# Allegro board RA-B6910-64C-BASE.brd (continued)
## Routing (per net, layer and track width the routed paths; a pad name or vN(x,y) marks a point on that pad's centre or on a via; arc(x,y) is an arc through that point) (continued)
VDD5V: length 15.8
  TOP w0.508: C113.1 387.09,55.17 ; R265.1 385.92,46.05 385.56,46.41 385.56,51.74 387.21,53.39 ; C114.2 387.09,54.03 ; R204.1 405.86,53.8 405.6,54.05 C103.1 v1(406.9,54.66)
  BOTTOM w0.381: v3(399.29,22.73) v1(400.18,22.73) ; v1(388.61,55.3) 388.62,55.31 v3(388.62,56.26) ; v1(406.9,54.66) 406.91,54.67 v3(406.91,55.75)
  vias: v1(390.01,55.3) v1(390.01,54.41) v1(390.01,53.52) v1(391.28,55.3) v1(398.64,24.31) v1(399.15,25.2) v1(399.53,24.31) v1(400.17,23.68)
VDD5V_EN: length 7.8
  TOP w0.381: Q7.3 407.79,57.08 406.67,55.96 R198.1 R193.2 403.88,55.96 403.09,55.17 U4.5
VDD12V: length 660.1
  TOP w0.381: R196.1 v1(412.61,56.21) ; C131.2 9.92,44.99 ; C131.2 11.39,44.99 ; C131.2 10.66,45.77 ; R262.1 v1(388.74,43.61) ; C79.2 v1(3.35,122.15) ; C151.2 47.77,45.11 ; C151.2 48.63,46.03 ; C151.2 49.37,45.11 ; R261.1 v1(395.59,42.98) ; C81.2 v1(4.88,122.15) ; R199.1 v1(413.76,52.5) ; R193.1 v1(404.61,57.84)
  TOP w0.508: J9.A18 24.52,127.07 ; J9.A18 25.68,125.91 ; J9.A18 24.52,124.76 ; J8.A16 387.06,125.91 ; J8.A16 385.9,124.76 ; J8.A16 384.74,125.91 ; J8.A16 385.9,127.07 ; J8.A13 393.52,127.07 ; J8.A13 393.52,124.76 ; J8.A13 394.68,125.91 ; J8.A13 392.36,125.91 ; J1.9 53.27,68.05 ; J1.9 50.24,68.05 ; J1.9 51.76,69.56 ; J1.9 51.76,66.54 ; 385.9,127.3 J8.B16 ; J8.B16 387.06,128.45 ; J8.B16 384.74,128.45 ; J5.8 113.04,170.95 ; J5.8 111.98,172.01 ; J5.8 110.92,170.95 ; 44.84,127.3 J9.B10 43.68,128.45 ; J3.9 15.76,69.56 ; J3.9 15.76,66.54 ; J3.9 17.27,68.05 ; J3.9 14.24,68.05 ; 42.3,124.76 J9.A11 ; J9.A11 41.14,125.91 ; J9.A11 43.46,125.91 ; J9.A11 42.3,127.07 ; 62.84,68.05 J1.6 ; J1.6 64.35,69.56 ; J1.6 65.87,68.05 ; J1.6 64.35,66.54 ; 19.96,66.54 J3.8 ; J3.8 21.47,68.05 ; J3.8 19.96,69.56 ; J3.8 18.44,68.05 ; J8.A12 396.06,127.07 ; J8.A12 397.22,125.91 ; J8.A12 396.06,124.76 ; J8.A12 394.9,125.91 ; 46.04,68.05 J1.10 ; J1.10 49.07,68.05 ; J1.10 47.55,69.56 ; J1.10 47.55,66.54 ; 26.84,68.05 J3.6 ; J3.6 29.87,68.05 ; J3.6 28.36,66.54 ; J3.6 28.36,69.56 ; J8.A15 389.6,125.91 ; J8.A15 388.44,124.76 ; J8.A15 388.44,127.07 ; J8.A15 387.28,125.91 ; 390.98,124.76 J8.A14 ; J8.A14 390.98,127.07 ; J8.A14 392.14,125.91 ; J8.A14 389.82,125.91 ; 58.64,68.05 J1.7 ; J1.7 61.67,68.05 ; J1.7 60.16,69.56 ; J1.7 60.16,66.54 ; 39.76,127.3 J9.B12 ; J9.B12 40.92,128.45 ; J9.B12 38.6,128.45 ; 37.22,127.3 J9.B13 ; J9.B13 36.06,128.45 ; J9.B13 38.38,128.45 ; C94.1 402.58,45.77 ; v1(363.52,121.77) 363.78,121.51 C68.2 ; 25.68,128.45 J9.B18 24.52,127.3 ; 208.76,170.95 J4.7 209.82,172.01 ; J9.A10 44.84,127.07 ; J9.A10 44.84,124.76 ; J9.A10 43.68,125.91 ; 11.55,66.54 J3.10 ; J3.10 11.55,69.56 ; J3.10 10.04,68.05 ; J3.10 13.07,68.05 ; 389.82,128.45 J8.B14 ; J8.B14 390.98,127.3 ; J8.B14 392.14,128.45 ; J9.A16 30.76,125.91 ; J9.A16 29.6,124.76 ; J9.A16 29.6,127.07 ; J9.A16 28.44,125.91 ; 113.46,170.95 J5.7 114.52,172.01 ; 383.36,124.76 J8.A17 ; J8.A17 382.2,125.91 ; J8.A17 384.52,125.91 ; J8.A17 383.36,127.07 ; 388.44,127.3 J8.B15 ; J8.B15 387.28,128.45 ; J8.B15 389.6,128.45 ; J8.B13 394.68,128.45 ; J8.B13 393.52,127.3 ; J8.B13 392.36,128.45 ; U9.A40 v1(165.71,50.13) ; 399.98,128.45 J8.B10 401.14,127.3 ; 32.14,127.3 J9.B15 ; J9.B15 30.98,128.45 ; J9.B15 33.3,128.45 ; 38.6,125.91 J9.A12 ; J9.A12 40.92,125.91 ; J9.A12 39.76,124.76 ; J9.A12 39.76,127.07 ; J8.A18 381.98,125.91 ; J8.A18 380.82,127.07 ; J8.A18 380.82,124.76 ; 398.6,127.3 J8.B11 ; J8.B11 397.44,128.45 ; J8.B11 399.76,128.45 ; 206.22,170.95 J4.8 ; J4.8 208.34,170.95 ; J4.8 207.28,172.01 ; 28.44,128.45 J9.B16 ; J9.B16 29.6,127.3 ; J9.B16 30.76,128.45 ; J9.A13 38.38,125.91 ; J9.A13 37.22,124.76 ; J9.A13 37.22,127.07 ; J9.A13 36.06,125.91 ; 34.68,124.76 J9.A14 ; J9.A14 35.84,125.91 ; J9.A14 34.68,127.07 ; J9.A14 33.52,125.91 ; 304.06,170.95 J2.7 305.12,172.01 ; 381.98,128.45 J8.B18 380.82,127.3 ; U9.B40 v1(164.44,50.13) ; 32.14,124.76 J9.A15 ; J9.A15 32.14,127.07 ; J9.A15 30.98,125.91 ; J9.A15 33.3,125.91 ; C67.2 v1(362.25,121.77) ; 396.06,127.3 J8.B12 ; J8.B12 397.22,128.45 ; J8.B12 394.9,128.45 ; J9.A17 27.06,127.07 ; J9.A17 28.22,125.91 ; J9.A17 27.06,124.76 ; J9.A17 25.9,125.91 ; J8.A11 398.6,127.07 ; J8.A11 399.76,125.91 ; J8.A11 397.44,125.91 ; J8.A11 398.6,124.76 ; J9.B11 43.46,128.45 ; J9.B11 41.14,128.45 ; J9.B11 42.3,127.3 ; 382.2,128.45 J8.B17 ; J8.B17 384.52,128.45 ; J8.B17 383.36,127.3 ; 27.06,127.3 J9.B17 ; J9.B17 28.22,128.45 ; J9.B17 25.9,128.45 ; 54.44,68.05 J1.8 ; J1.8 55.95,66.54 ; J1.8 57.47,68.05 ; J1.8 55.95,69.56 ; J2.8 302.58,172.01 ; J2.8 301.52,170.95 ; J2.8 303.64,170.95 ; U9.D40 161.9,50.16 v1(161.91,50.15) ; v1(163.18,50.15) 163.17,50.16 U9.C40 ; J8.A10 401.14,127.07 ; J8.A10 399.98,125.91 ; J8.A10 401.14,124.76 ; 22.64,68.05 J3.7 ; J3.7 24.16,69.56 ; J3.7 24.16,66.54 ; J3.7 25.67,68.05 ; 33.52,128.45 J9.B14 ; J9.B14 34.68,127.3 ; J9.B14 35.84,128.45 ; C108.1 v1(398.64,52.76)
  TOP w0.559: U3.3 402.13,43.8 402.45,44.12 ; v1(397.63,53.9) 397.95,54.22 U4.3
  GND1 w0.508: 382.2,128.45 J8.B17 ; J8.B17 384.52,128.45 ; J8.B17 383.36,129.61 ; J8.B17 383.36,127.3 ; J8.A13 393.52,127.07 ; J8.A13 392.36,125.91 ; J8.A13 394.68,125.91 ; J8.A13 393.52,124.76 ; J8.A18 381.98,125.91 ; J8.A18 380.82,127.07 ; J8.A18 380.82,124.76 ; 398.6,127.3 J8.B11 ; J8.B11 397.44,128.45 ; J8.B11 399.76,128.45 ; J8.B11 398.6,129.61 ; J8.A14 392.14,125.91 ; J8.A14 390.98,124.76 ; J8.A14 390.98,127.07 ; J8.A14 389.82,125.91 ; J8.A11 399.76,125.91 ; J8.A11 398.6,127.07 ; J8.A11 397.44,125.91 ; J8.A11 398.6,124.76 ; 384.74,128.45 J8.B16 ; J8.B16 385.9,127.3 ; J8.B16 385.9,129.61 ; J8.B16 387.06,128.45 ; J8.B12 396.06,129.61 ; J8.B12 397.22,128.45 ; J8.B12 394.9,128.45 ; J8.B12 396.06,127.3 ; J8.A15 388.44,127.07 ; J8.A15 389.6,125.91 ; J8.A15 387.28,125.91 ; J8.A15 388.44,124.76 ; J8.B15 389.6,128.45 ; J8.B15 388.44,127.3 ; J8.B15 388.44,129.61 ; J8.B15 387.28,128.45 ; J8.A16 387.06,125.91 ; J8.A16 384.74,125.91 ; J8.A16 385.9,127.07 ; J8.A16 385.9,124.76 ; J8.B13 393.52,129.61 ; J8.B13 393.52,127.3 ; J8.B13 394.68,128.45 ; J8.B13 392.36,128.45 ; J8.B14 392.14,128.45 ; J8.B14 390.98,129.61 ; J8.B14 390.98,127.3 ; J8.B14 389.82,128.45 ; 396.06,124.76 J8.A12 ; J8.A12 394.9,125.91 ; J8.A12 397.22,125.91 ; J8.A12 396.06,127.07 ; J8.A17 383.36,127.07 ; J8.A17 384.52,125.91 ; J8.A17 383.36,124.76 ; J8.A17 382.2,125.91 ; 399.98,125.91 J8.A10 ; J8.A10 401.14,127.07 ; J8.A10 401.14,124.76 ; 399.98,128.45 J8.B10 ; J8.B10 401.14,127.3 ; J8.B10 401.14,129.61 ; 380.82,127.3 J8.B18 381.98,128.45
  SIG1 w0.508: 60.16,66.54 J1.7 ; J1.7 60.16,69.56 ; J1.7 58.64,68.05 ; J1.7 61.67,68.05 ; J8.A14 392.14,125.91 ; J8.A14 390.98,124.76 ; J8.A14 390.98,127.07 ; J8.A14 389.82,125.91 ; 51.76,66.54 J1.9 ; J1.9 51.76,69.56 ; J1.9 53.27,68.05 ; J1.9 50.24,68.05 ; J9.B13 38.38,128.45 ; J9.B13 36.06,128.45 ; J9.B13 37.22,127.3 ; J9.B14 35.84,128.45 ; J9.B14 33.52,128.45 ; J9.B14 34.68,127.3 ; 24.52,127.3 J9.B18 25.68,128.45 ; J1.8 55.95,69.56 ; J1.8 55.95,66.54 ; J1.8 57.47,68.05 ; J1.8 54.44,68.05 ; 64.35,66.54 J1.6 ; J1.6 62.84,68.05 ; J1.6 65.87,68.05 ; J1.6 64.35,69.56 ; 34.68,124.76 J9.A14 ; J9.A14 33.52,125.91 ; J9.A14 34.68,127.07 ; J9.A14 35.84,125.91 ; 385.9,124.76 J8.A16 ; J8.A16 385.9,127.07 ; J8.A16 387.06,125.91 ; J8.A16 384.74,125.91 ; J9.A17 28.22,125.91 ; J9.A17 25.9,125.91 ; J9.A17 27.06,127.07 ; J9.A17 27.06,124.76 ; 14.24,68.05 J3.9 ; J3.9 15.76,66.54 ; J3.9 17.27,68.05 ; J3.9 15.76,69.56 ; J9.A16 29.6,127.07 ; J9.A16 28.44,125.91 ; J9.A16 30.76,125.91 ; J9.A16 29.6,124.76 ; J9.A12 40.92,125.91 ; J9.A12 39.76,127.07 ; J9.A12 39.76,124.76 ; J9.A12 38.6,125.91 ; J9.A15 32.14,127.07 ; J9.A15 32.14,124.76 ; J9.A15 30.98,125.91 ; J9.A15 33.3,125.91 ; J8.A18 381.98,125.91 ; J8.A18 380.82,124.76 ; J8.A18 380.82,127.07 ; J9.A18 25.68,125.91 ; J9.A18 24.52,127.07 ; J9.A18 24.52,124.76 ; 46.04,68.05 J1.10 ; J1.10 47.55,69.56 ; J1.10 47.55,66.54 ; J1.10 49.07,68.05 ; 396.06,124.76 J8.A12 ; J8.A12 394.9,125.91 ; J8.A12 397.22,125.91 ; J8.A12 396.06,127.07 ; 41.14,125.91 J9.A11 ; J9.A11 42.3,127.07 ; J9.A11 42.3,124.76 ; J9.A11 43.46,125.91 ; J8.A11 398.6,127.07 ; J8.A11 397.44,125.91 ; J8.A11 398.6,124.76 ; J8.A11 399.76,125.91 ; 392.36,125.91 J8.A13 ; J8.A13 393.52,124.76 ; J8.A13 394.68,125.91 ; J8.A13 393.52,127.07 ; 10.04,68.05 J3.10 ; J3.10 13.07,68.05 ; J3.10 11.55,66.54 ; J3.10 11.55,69.56 ; J3.7 25.67,68.05 ; J3.7 24.16,66.54 ; J3.7 24.16,69.56 ; J3.7 22.64,68.05 ; J8.A10 401.14,127.07 ; J8.A10 401.14,124.76 ; J8.A10 399.98,125.91 ; 36.06,125.91 J9.A13 ; J9.A13 37.22,124.76 ; J9.A13 37.22,127.07 ; J9.A13 38.38,125.91 ; 399.98,128.45 J8.B10 401.14,127.3 ; J9.B12 40.92,128.45 ; J9.B12 38.6,128.45 ; J9.B12 39.76,127.3 ; 28.44,128.45 J9.B16 ; J9.B16 30.76,128.45 ; J9.B16 29.6,127.3 ; 396.06,127.3 J8.B12 ; J8.B12 394.9,128.45 ; J8.B12 397.22,128.45 ; J9.B15 33.3,128.45 ; J9.B15 32.14,127.3 ; J9.B15 30.98,128.45 ; J8.B16 387.06,128.45 ; J8.B16 384.74,128.45 ; J8.B16 385.9,127.3 ; 387.28,128.45 J8.B15 ; J8.B15 389.6,128.45 ; J8.B15 388.44,127.3 ; 382.2,125.91 J8.A17 ; J8.A17 383.36,127.07 ; J8.A17 383.36,124.76 ; J8.A17 384.52,125.91 ; J3.8 19.96,69.56 ; J3.8 19.96,66.54 ; J3.8 18.44,68.05 ; J3.8 21.47,68.05 ; 44.84,124.76 J9.A10 ; J9.A10 44.84,127.07 ; J9.A10 43.68,125.91 ; 44.84,127.3 J9.B10 43.68,128.45 ; 28.36,66.54 J3.6 ; J3.6 28.36,69.56 ; J3.6 26.84,68.05 ; J3.6 29.87,68.05 ; J9.B11 43.46,128.45 ; J9.B11 41.14,128.45 ; J9.B11 42.3,127.3 ; J9.B17 28.22,128.45 ; J9.B17 25.9,128.45 ; J9.B17 27.06,127.3 ; J8.B13 394.68,128.45 ; J8.B13 393.52,127.3 ; J8.B13 392.36,128.45 ; 387.28,125.91 J8.A15 ; J8.A15 388.44,124.76 ; J8.A15 388.44,127.07 ; J8.A15 389.6,125.91 ; 397.44,128.45 J8.B11 ; J8.B11 398.6,127.3 ; J8.B11 399.76,128.45 ; 389.82,128.45 J8.B14 ; J8.B14 390.98,127.3 ; J8.B14 392.14,128.45 ; 383.36,127.3 J8.B17 ; J8.B17 384.52,128.45 ; J8.B17 382.2,128.45 ; 380.82,127.3 J8.B18 381.98,128.45
  SIG1 w1.016: J8.A24 365.58,123.75
  SIG2 w0.508: 58.64,68.05 J1.7 ; J1.7 61.67,68.05 ; J1.7 60.16,66.54 ; J1.7 60.16,69.56 ; 41.14,125.91 J9.A11 ; J9.A11 43.46,125.91 ; J9.A11 42.3,124.76 ; J9.A11 42.3,127.07 ; J3.7 24.16,69.56 ; J3.7 25.67,68.05 ; J3.7 24.16,66.54 ; J3.7 22.64,68.05 ; 11.55,66.54 J3.10 ; J3.10 10.04,68.05 ; J3.10 13.07,68.05 ; J3.10 11.55,69.56 ; J9.A15 33.3,125.91 ; J9.A15 32.14,124.76 ; J9.A15 30.98,125.91 ; J9.A15 32.14,127.07 ; J9.B16 30.76,128.45 ; J9.B16 28.44,128.45 ; J9.B16 29.6,127.3 ; 50.24,68.05 J1.9 ; J1.9 51.76,69.56 ; J1.9 51.76,66.54 ; J1.9 53.27,68.05 ; J9.B17 28.22,128.45 ; J9.B17 27.06,127.3 ; J9.B17 25.9,128.45 ; 15.76,66.54 J3.9 ; J3.9 15.76,69.56 ; J3.9 14.24,68.05 ; J3.9 17.27,68.05 ; 64.35,66.54 J1.6 ; J1.6 64.35,69.56 ; J1.6 62.84,68.05 ; J9.A12 39.76,127.07 ; J9.A12 39.76,124.76 ; J9.A12 40.92,125.91 ; J9.A12 38.6,125.91 ; 33.52,125.91 J9.A14 ; J9.A14 34.68,127.07 ; J9.A14 35.84,125.91 ; J9.A14 34.68,124.76 ; J9.A16 29.6,127.07 ; J9.A16 30.76,125.91 ; J9.A16 28.44,125.91 ; J9.A16 29.6,124.76 ; 39.76,127.3 J9.B12 ; J9.B12 38.6,128.45 ; J9.B12 40.92,128.45 ; 42.3,127.3 J9.B11 ; J9.B11 43.46,128.45 ; J9.B11 41.14,128.45 ; 25.68,128.45 J9.B18 24.52,127.3 ; J9.A13 37.22,127.07 ; J9.A13 36.06,125.91 ; J9.A13 38.38,125.91 ; J9.A13 37.22,124.76 ; 43.68,125.91 J9.A10 ; J9.A10 44.84,127.07 ; J9.A10 44.84,124.76 ; J9.A18 25.68,125.91 ; J9.A18 24.52,127.07 ; J9.A18 24.52,124.76 ; 55.95,66.54 J1.8 ; J1.8 55.95,69.56 ; J1.8 57.47,68.05 ; J1.8 54.44,68.05 ; 32.14,127.3 J9.B15 ; J9.B15 33.3,128.45 ; J9.B15 30.98,128.45 ; 26.84,68.05 J3.6 ; J3.6 28.36,69.56 ; J3.6 28.36,66.54 ; J3.6 29.87,68.05 ; 33.52,128.45 J9.B14 ; J9.B14 35.84,128.45 ; J9.B14 34.68,127.3 ; 27.06,124.76 J9.A17 ; J9.A17 28.22,125.91 ; J9.A17 27.06,127.07 ; J9.A17 25.9,125.91 ; 19.96,66.54 J3.8 ; J3.8 18.44,68.05 ; J3.8 19.96,69.56 ; J3.8 21.47,68.05 ; 36.06,128.45 J9.B13 ; J9.B13 37.22,127.3 ; J9.B13 38.38,128.45 ; J1.10 49.07,68.05 ; J1.10 47.55,66.54 ; J1.10 46.04,68.05 ; J1.10 47.55,69.56 ; 44.84,127.3 J9.B10 43.68,128.45
  SIG2 w1.016: 9.28,124.15 J9.A24
  BOTTOM w0.381: v3(392.68,106.43) 392.68,107.74 v4(392.67,107.75) ; v3(53.72,114.05) 53.72,115.74 v4(53.71,115.75) ; v1(403.21,46.79) 403.21,48 v3(403.23,48.01) ; v3(314.58,99.19) 314.58,98.11 v1(314.57,98.1) ; v3(46.47,114.05) v4(46.47,115.75) ; v4(28.82,115.75) 28.83,115.74 v3(28.83,114.17) ; v3(317.25,99.19) 317.25,98.11 v1(317.24,98.1) ; v3(389.13,106.43) 389.13,107.87 v4(389.12,107.88) ; v3(399.8,52.7) 398.7,52.7 v1(398.64,52.76) ; v4(385.94,109.15) 385.89,109.09 v3(384.18,109.09) ; v3(36.45,114.3) 36.45,115.74 v4(36.44,115.75) ; v1(319.9,98.1) 319.91,98.11 v3(319.91,99.19) ; v3(60.83,114.3) 60.83,115.74 v4(60.82,115.75) ; v1(395.21,52.76) 395.27,52.7 v3(396.37,52.7) ; v4(397.75,107.75) 397.76,107.74 v3(397.76,106.43)
  vias: v1(314.57,97.21) v1(314.57,96.32) v1(314.57,95.43) v1(315.46,98.1) v1(315.46,97.21) v1(315.46,96.32) v1(315.46,95.43) v1(316.35,98.1) v1(316.35,97.21) v1(316.35,96.32) v1(316.35,95.43) v1(317.24,97.21) v1(317.24,96.32) v1(317.24,95.43) v1(318.12,98.1) v1(318.12,97.21) v1(318.12,96.32) v1(318.12,95.43) v1(319.01,98.1) v1(319.01,97.21) v1(319.01,96.32) v1(319.01,95.43) v1(319.9,97.21) v1(319.9,96.32) v1(319.9,95.43) v1(320.79,98.1) v1(320.79,97.21) v1(320.79,96.32) v1(320.79,95.43) v1(321.68,98.1) v1(321.68,97.21) v1(321.68,96.32) v1(321.68,95.43) v1(395.21,53.65) v1(397.5,52.76) v1(403.21,45.65) v1(403.21,44.5) v1(404.23,46.79) v4(28.63,123.67) v4(28.75,120.11) v4(28.82,117.78) v4(29.77,121.89) v4(31.17,123.67) v4(31.29,120.11) v4(31.36,117.78) v4(31.36,115.75) v4(32.31,121.89) v4(33.71,123.67) v4(33.83,120.11) v4(33.9,117.78) v4(33.9,115.75) v4(34.85,121.89) v4(36.25,123.67) v4(36.37,120.11) v4(36.44,117.78) v4(37.39,121.89) v4(38.79,123.67) v4(38.91,120.11) v4(38.98,117.78) v4(38.98,115.75) v4(39.93,121.89) v4(41.33,123.67) v4(41.45,120.11) v4(41.52,117.78) v4(41.52,115.75) v4(42.47,121.89) v4(43.74,123.67) v4(43.87,120.11) v4(43.93,117.78) v4(43.93,115.75) v4(45.01,121.89) v4(46.41,123.42) v4(46.53,119.86) v4(46.47,117.78) v4(47.55,121.38) v4(48.82,122.91) v4(48.82,119.86) v4(48.76,117.78) v4(48.76,115.75) v4(50.09,121.38) v4(51.23,119.86) v4(51.17,117.78) v4(51.17,115.75) v4(51.36,122.91) v4(52.63,121.38) v4(53.71,117.78) v4(53.77,119.86) v4(53.9,122.91) v4(55.17,121.38) v4(55.93,119.81) v4(55.87,117.78) v4(55.87,115.75) v4(56.13,122.94) v4(57.33,121.51) v4(58.34,119.86) v4(58.28,117.78) v4(58.28,115.75) v4(58.6,123.04) v4(59.87,121.51) v4(60.82,117.78) v4(60.88,119.86) v4(61.14,123.04) v4(62.41,121.51) v4(63.11,117.78) v4(63.11,115.75) v4(63.17,119.86) v4(63.68,123.04) v4(64.95,121.64) v4(65.65,117.78) v4(65.71,119.86) v4(66.22,123.04) v4(67.49,121.64) v4(67.93,119.69) v4(68.76,123.04) v4(69.9,121.64) v4(385.75,123.42) v4(385.75,121.64) v4(385.82,119.81) v4(385.94,117.53) v4(385.94,116.13) v4(385.94,114.61) v4(385.94,113.21) v4(385.94,111.94) v4(385.94,110.54) v4(385.94,107.88) v4(387.59,117.53) v4(387.59,116.13) v4(387.59,114.61) v4(387.59,113.21) v4(387.59,111.94) v4(387.59,110.54) v4(387.59,109.15) v4(387.59,107.88) v4(388.29,123.42) v4(388.29,121.64) v4(388.36,119.81) v4(389.12,117.53) v4(389.12,116.13) v4(389.12,114.61) v4(389.12,113.21) v4(389.12,111.94) v4(389.12,110.54) v4(389.12,109.15) v4(390.83,123.42) v4(390.83,121.64) v4(390.9,117.4) v4(390.9,116) v4(390.9,114.48) v4(390.9,113.08) v4(390.9,111.81) v4(390.9,110.42) v4(390.9,109.02) v4(390.9,107.75) v4(392.67,117.4) v4(392.67,116) v4(392.67,114.48) v4(392.67,113.08) v4(392.67,111.81) v4(392.67,110.42) v4(392.67,109.02) v4(393.37,123.42) v4(393.37,121.64) v4(393.44,119.81) v4(394.32,117.4) v4(394.32,116) v4(394.32,114.48) v4(394.32,113.08) v4(394.32,111.81) v4(394.32,110.42) v4(394.32,109.02) v4(394.32,107.75) v4(395.91,123.42) v4(395.91,121.64) v4(395.98,119.81) v4(395.98,117.4) v4(395.98,116) v4(395.98,114.48) v4(395.98,113.08) v4(395.98,111.81) v4(395.98,110.42) v4(395.98,109.02) v4(395.98,107.75) v4(397.69,121.64) v4(397.75,119.81) v4(397.75,117.4) v4(397.75,116) v4(397.75,114.48) v4(397.75,113.08) v4(397.75,111.81) v4(397.75,110.42) v4(397.75,109.02)
VDD12VSB: length 403.6
  TOP w0.305: 371.91,124 371.91,127.16 J8.B21 ; J9.B21 15.62,127.18 15.62,124.38
  TOP w0.508: 371.91,124 369.62,121.72 C77.2 368.73,120.95 368.63,120.85 v2(368.48,120.85) C74.2 ; 15.62,124.38 13.72,122.48 13.1,122.48 12.12,121.5 C87.2 13.09,120.98 13.19,121.08 C89.2 15.06,121.08 15.8,120.34 v1(15.8,116.71) 15.8,115.84 22.11,109.53 78.23,109.53 v1(79.84,111.14)
  SIG2 w0.508: v1(79.84,111.14) 84.42,115.72 85.91,115.72 89.78,119.59 92.28,119.59 95.94,123.25 99.57,123.25 100.19,123.87 103.92,123.87 104.23,124.19 109.21,124.19 109.59,124.57 114.73,124.57 120.13,119.17 120.13,118.55 126.03,112.65 144.72,112.65 146.29,114.23 157.34,114.23 160.64,110.92 340.98,110.92 348.4,118.34 359.97,118.34 361.59,119.96 365.37,119.96 366.26,120.85 v2(368.48,120.85)
  BOTTOM w0.381: v1(15.8,116.71) 15.8,116.28 v3(16.38,115.7)
9548_RST#: length 37
  TOP w0.201: R128.2 v2(128.39,152.83) ; R240.2 v1(97.91,153.09) 98.02,152.97 U8.3
  SIG1 w0.15: v1(108.83,152.58) 105.15,152.58 104.38,153.34 98.16,153.34 v1(97.91,153.09)
  SIG2 w0.16: v2(128.39,152.83) 127.88,153.34 121.97,153.34 120.92,154.39 119.97,154.39 119.06,155.3 115.65,155.3 115.25,154.9 111.15,154.9 v1(108.83,152.58)
ALL_RESET#: length 197.3
  TOP w0.201: U1.107 117.47,149.78 116.96,150.29 R109.1 116.55,151.21 116.37,151.39 116.37,153.06 116.96,153.65 R110.1 113.3,153.88 v2(112.89,153.47) ; U9.C26 162.55,69.4 161.58,69.4 159.37,67.19 v1(159.37,64.84)
  SIG2 w0.16: v2(112.89,153.47) 111.64,153.47 105.64,147.47 105.64,136.87 103.24,134.47 103.24,130.58 101.84,129.17 95.02,129.17 91.15,125.31 90.47,125.31 89.18,124.02 84.22,124.02 72.61,112.41 72.61,100 83.6,89.01 96.83,89.01 98.45,87.4 122.26,87.4 139.43,70.22 148.26,70.22 153.64,64.84 v1(159.37,64.84)
BMC_9641_INT#: length 121.9
  TOP w0.201: U9.A2 166.25,99.82 v1(174.93,99.82) ; v2(105.17,134.5) 104.87,134.8 R303.1
  SIG1 w0.15: v1(174.93,99.82) 174.93,126.38 173.94,127.37 150.47,127.37 141.9,118.8 124.96,118.8 123.18,120.59 118.15,120.59 113.78,124.95 113.78,133.28 113.02,134.04 112,134.04 111.54,134.5 v2(105.17,134.5)
BMC_I2C_RST#: length 208.2
  TOP w0.201: U9.D36 159.73,56.09 v1(158.99,56.82) ; v2(122.43,155.07) 122.43,155.57 122.76,155.91 R117.2
  SIG2 w0.16: v1(158.99,56.82) 157.56,56.82 148.38,65.99 139.13,65.99 120.8,84.32 83.42,84.32 69.54,98.2 69.54,113.69 83.57,127.71 87.85,127.71 88.81,128.67 90.17,128.67 92.09,130.59 92.09,131.77 92.57,132.25 94.34,132.25 94.6,132.51 99.75,132.51 100.17,132.93 100.17,136.37 103.6,139.8 103.6,150.45 109.78,156.64 112.01,156.64 112.83,157.46 120.82,157.46 122.43,155.85 v2(122.43,155.07)
BMC_I2C_SCL: length 194.7
  TOP w0.127: v1(163.8,63.07) 163.8,60.53 U9.B33
  TOP w0.201: R309.2 90.03,126.8 89.5,127.34 v1(89.45,127.34) ; U10.5 101.91,133.35 102.59,134.02 105.57,134.02 105.68,134.13 105.68,136.55 104.89,137.34 104.3,137.34 v2(103.98,137.67) 104.92,138.61 107.05,138.61 107.71,137.95 109.31,137.95 109.44,138.08 R115.1 109.86,138.48 110.57,137.77 112.57,137.77 112.89,138.1 U1.126
  SIG2 w0.16: v2(103.98,137.67) 101.5,135.19 101.5,132.36 100.05,130.91 94.3,130.91 90.72,127.34 v1(89.45,127.34) 89.45,126.74 89.09,126.38 84.12,126.38 70.88,113.13 70.88,98.76 83.98,85.66 121.36,85.66 139.69,67.33 148.94,67.33 153.31,62.96 161.25,62.96 161.81,63.52 163.4,63.52 163.8,63.12 v1(163.8,63.07)
BMC_I2C_SDA: length 182.9
  TOP w0.127: U9.D33 v1(161.26,59.26)
  TOP w0.201: R301.1 104.49,136.22 104.13,136.58 103.72,136.58 v2(102.68,137.62) 102.65,137.64 102.65,137.92 104.83,140.09 109.25,140.09 109.44,139.91 R123.1 109.84,139.5 110.86,138.48 R16.2 ; R310.2 91.05,126.99 v1(90.03,128)
  SIG2 w0.16: v2(102.68,137.62) 100.84,135.78 100.84,132.65 100.03,131.84 95.33,131.84 95.07,131.59 94.03,131.59 90.45,128 v1(90.03,128) 89.09,128 88.13,127.05 83.84,127.05 70.21,113.41 70.21,98.48 83.7,84.99 121.08,84.99 139.41,66.66 148.66,66.66 153.03,62.29 158.23,62.29 v1(161.26,59.26)
BMC_RESERVE1: length 120.4
  TOP w0.127: U9.C38 v1(162.53,52.91)
  TOP w0.201: v2(147.01,122.35) 147.01,127.62 145.67,128.96 R249.2
  SIG1 w0.15: v2(147.01,122.35) 151.18,126.52 173.32,126.52 173.98,125.85 173.98,60.75 168.83,55.6 168.83,54.13 167.17,52.47 164.02,52.47 163.57,52.91 v1(162.53,52.91)
CPLD3.3V: length 529.5
  TOP w0.229: C17.1 135.09,124.36 134.79,124.67 134.79,126.24 134.47,126.56 U1.36 ; C8.2 126.94,151.21 126.69,150.95 126.69,149.84 126.97,149.55 U1.88 ; v1(138.29,128.83) 138.03,129.1 U1.37 ; U1.102 119.97,150.79 C9.2 ; U1.7 119.97,125.91 119.75,125.69 v1(119.75,125.2) ; v1(113.02,139.6) U1.123 ; U1.30 131.47,125.82 131.05,125.4 v1(131.05,125.02) ; U1.108 116.97,149.24 116.42,149.79 115.94,149.79 v1(115.31,150.42) ; U1.144 112.65,129.1 112.51,128.96 C6.2 ; C48.2 124.32,124.61 124.32,125.91 124.47,126.06 U1.16 ; U1.79 131.47,149.62 131.03,150.07 131.03,151.03 131.21,151.21 C2.2 ; v1(137.91,135.69) 137.5,136.1 U1.51 ; U1.135 113.77,133.6 113.2,133.02 v1(112.79,133.02) ; C4.2 138.57,143.69 137.53,143.69 137.44,143.6 U1.66 ; v1(113.53,141.91) 113.71,142.1 U1.118 ; U1.72 138.15,146.6 138.67,147.12 C3.2
  TOP w0.254: C117.2 99.32,143.01 U8.24 ; U2.20 57.01,84.38 56.63,84 C63.2
  TOP w0.305: U10.16 94.36,130.75 93.33,129.72 C154.2
  TOP w0.381: v1(235.07,175.85) R346.1 234.28,175.82 R347.2 ; R299.2 v1(90.92,134.47) ; 142.74,87.43 141.13,89.04 141.13,91.66 143.75,94.29 R256.2 R275.2 R274.2 ; 142.74,87.43 144.41,89.11 R257.2 ; 142.74,87.43 142.74,82.35 142.74,82.35 142.74,80.8 144.42,79.13 R258.1 143.63,78.35 142.74,77.46 142.74,65.16 143.33,64.57 R260.1 144.41,58.57 144.42,58.57 v1(144.42,53.87) ; R296.2 v1(90.92,135.82) ; R160.2 134.23,122.86 v1(134.48,122.61) ; R318.2 v1(107.94,135.69) ; R283.1 110.23,157.94 v1(109.72,158.45) ; v1(107.81,145.16) 108.13,145.47 R133.1 ; R230.1 94.99,155.25 v1(95.37,155.63) ; R352.2 139.05,164.8 R351.1 v1(139.08,163.88) ; C6.2 C22.2 ; C22.2 v1(112.89,127.94) ; C22.2 C19.2 ; R113.2 v1(119.24,152.83) ; R17.2 110.66,140.52 v1(110.35,140.82) ; R166.2 119.75,120.07 ; v1(153.44,173.07) 153.29,172.93 U7.8 ; v1(142.33,146.74) R273.2 ; R232.1 v1(92.7,155.63) ; C9.2 120.39,150.68 v1(120.64,150.42) ; R242.1 v1(99.94,155.63) R284.2 ; R158.2 122.67,120.13 ; v1(138.29,143.06) 138.7,143.06 C4.2 ; R255.1 v1(53.71,89.72) ; R143.2 v1(134.97,152.17) ; R89.2 v1(107.69,141.91) ; R294.2 91.05,137.09 v1(90.92,136.96) ; v1(129.66,120.58) R277.1 R333.2 ; R243.1 96.89,138.99 v1(95.87,137.98) ; C154.2 C155.2 92.55,127.92 92.32,127.69 91.3,127.69 89.04,129.95 v1(89.04,130.02) 89.02,130.04 R304.1 ; C116.1 154.2,173.71 v1(153.95,173.96) ; R161.2 v1(133.21,122.61) ; R329.2 329.15,173.03 R328.1 v1(329.94,173.05) ; R271.2 v1(140.58,145.09) ; R131.1 v1(107.81,144.2) ; R47.2 v1(34.15,85.4) ; v1(138.29,127.82) C49.2 C157.2 ; C51.2 v1(119.75,125.2) ; R164.2 v1(126.99,122.61) ; R345.2 117.08,120.45 117.85,119.69 ; R356.2 v1(132.68,54.05) ; R150.1 v1(53.71,85.65) ; R154.2 121.02,120.16 ; C3.2 C7.2 v1(138.17,148.14) ; R268.2 142.33,132.5 v1(142.52,132.69) 142.33,132.88 R270.2 ; R292.2 91.05,138.48 v1(90.92,138.36) ; 124.58,120.2 R339.2 125.19,120.86 ; D2.3 v1(110.1,147.53) ; R122.2 v1(123.81,152.83) ; C2.2 131.56,150.78 v1(131.82,150.52) ; C63.2 v1(55.46,83.11) ; R240.1 v1(97.91,155.63) ; R46.2 v1(34.15,94.16) ; C20.2 C5.2 v1(136.39,125.15) ; R254.1 v1(53.71,86.67) ; C66.1 C1.2 114.8,150.93 v1(115.31,150.42) ; C117.2 v1(99.94,143.18) ; C10.2 v1(34.15,90.1) ; C65.1 v1(113.53,141.91) ; v1(127.98,122.68) 128.13,122.83 R163.2 ; R252.1 v1(68.06,89.08) ; R229.1 v1(95.37,158.3) ; C48.2 124.58,124.51 v1(125.08,125.02) ; R115.2 R123.2 v1(107.69,139.5) ; v1(137.91,135.69) 138.67,134.93 C23.2 ; R112.2 v1(144.01,124.89) ; R305.2 90.41,130.74 v1(90.29,130.86) ; C64.1 112.92,139.5 v1(113.02,139.6) ; v1(156.36,169.52) R224.2 R225.2 ; v1(138.29,128.83) C16.1 ; C92.1 394.99,44.86 394.73,45.11 R195.1 ; C17.1 135.24,125 v1(135.4,125.15) ; C8.2 v1(127.24,150.42) ; R110.2 116.12,154.84 v1(115.94,154.66) ; v1(112.79,133.02) C21.2 ; R167.2 v1(121.02,122.61) ; v1(105.27,132.51) R297.1 ; R231.1 v1(92.7,158.3) ; C18.1 v1(138.17,149.15) ; C156.1 v1(115.81,152.96) ; v1(131.05,125.02) C50.2 ; R220.2 v1(156.36,171.55) ; R319.2 v1(107.94,136.96) ; R306.1 88.25,133.53 v1(87.87,133.91) ; R241.1 v1(100.95,155.63) ; R228.1 v1(96.64,155.63) ; v1(110.35,130.99) R118.2 ; R281.2 v1(236.21,169.22) ; R227.1 v1(97.41,157.51)
  TOP w0.508: C92.1 393.94,44.25 393.67,44.52 393.67,48.3 394.07,48.69 401.56,48.69 402.45,49.58 v1(412.61,49.58) ; 414.14,39.55 415.15,38.53 X22.1 ; v1(413.5,44.12) 413.37,44.25 C100.2 ; 414.26,44 414.52,44.25 C99.1 ; C97.1 410.45,44.78 v1(411.24,44) ; v1(229.89,167.95) R280.1 228.72,167.19 228.18,166.65 214.21,166.65 v1(212.59,165.03) ; v1(304.79,166.3) 306.34,164.75 v1(322.6,164.75) 326.86,164.75 327.52,165.41 R278.2 ; R194.1 414.49,40.85 ; C98.1 411.98,44.25
  TOP w1.016: v4(67.68,81.46) v4(55.46,81.46) 52.95,81.46 50.41,84 v4(34.15,84) 26.15,84 23.74,86.41 23.74,90.1 24.75,91.11 J7.4
  SIG1 w0.381: v1(329.94,173.05) 329.94,172.09 v1(322.6,164.75) ; v1(68.06,89.08) 67.21,88.23 67.21,84.6 67.68,84.13 v4(67.68,81.46)
  SIG1 w0.508: v4(55.46,81.46) v1(55.46,83.11) 55.46,83.52 53.71,85.27 v1(53.71,85.65) v1(53.71,86.67) v1(53.71,89.72) ; v1(235.07,175.85) 235.07,175.16 229.89,169.98 v1(229.89,167.95) ; v4(34.15,84) v1(34.15,85.4) 34.79,86.03 34.79,89.46 v1(34.15,90.1) v1(34.15,94.16)
  SIG2 w0.381: v1(139.08,163.88) 136.13,160.94 136.13,153.22
  SIG2 w0.508: 161.28,168.2 181.22,168.2 184.39,165.03 v1(212.59,165.03) ; v1(229.89,167.95) 234.94,167.95 v1(236.21,169.22) 239.38,169.22 241.61,166.99 304.1,166.99 v1(304.79,166.3)
  vias: v1(126.14,120.61) v1(127.16,120.61) v1(128.13,120.61) v1(159.5,168.71) v1(159.5,167.57) v1(160.14,154.87) v1(160.14,153.98) v1(160.52,168.71) v1(160.52,167.57) v1(161.15,154.87) v1(161.15,153.98) v1(188.46,53.14) v1(188.46,52.25) v1(188.46,51.36) v1(188.46,50.47) v1(189.35,53.14) v1(189.35,52.25) v1(189.35,51.36) v1(189.35,50.47) v1(189.85,102.29) v1(189.85,101.4) v1(189.85,100.51) v1(189.85,99.62) v1(190.24,53.14) v1(190.24,52.25) v1(190.24,51.36) v1(190.24,50.47) v1(190.36,123.62) v1(190.36,122.74) v1(190.36,121.85) v1(190.36,120.96) v1(190.74,102.29) v1(190.74,101.4) v1(190.74,100.51) v1(190.74,99.62) v1(191.12,53.14) v1(191.12,52.25) v1(191.12,51.36) v1(191.12,50.47) v1(191.25,123.62) v1(191.25,122.74) v1(191.25,121.85) v1(191.25,120.96) v1(191.63,102.29) v1(191.63,101.4) v1(191.63,100.51) v1(191.63,99.62) v1(192.01,53.14) v1(192.01,52.25) v1(192.01,51.36) v1(192.01,50.47) v1(192.14,123.62) v1(192.14,122.74) v1(192.14,121.85) v1(192.14,120.96) v1(192.52,102.29) v1(192.52,101.4) v1(192.52,100.51) v1(192.52,99.62) v1(192.9,53.14) v1(192.9,52.25) v1(192.9,51.36) v1(192.9,50.47) v1(193.03,123.62) v1(193.03,122.74) v1(193.03,121.85) v1(193.03,120.96) v1(193.41,102.29) v1(193.41,101.4) v1(193.41,100.51) v1(193.41,99.62) v1(193.92,123.62) v1(193.92,122.74) v1(193.92,121.85) v1(193.92,120.96) v1(194.3,102.29) v1(194.3,101.4) v1(194.3,100.51) v1(194.3,99.62) v1(194.81,123.62) v1(194.81,122.74) v1(194.81,121.85) v1(194.81,120.96) v1(412.61,44.12) v1(413.5,42.98)
CPLD3.3V_EN: length 8.5
  TOP w0.381: Q9.3 v1(393.16,41.71) 393.51,41.35 R264.1 R261.2 396.13,41.35 396.51,41.73 396.51,42.12 397.25,42.85 U3.5
  BOTTOM w0.381: v3(392.3,41.78) 393.08,41.78 v1(393.16,41.71)
CPLD_DOWNLOAD_OK: length 10.1
  TOP w0.201: U1.106 117.97,150.17 117.49,150.65 117.49,155.27 118.1,155.88 R119.1 117.43,156.16 v1(117.09,155.83)
  BOTTOM w0.201: v1(117.09,155.83) 116.97,155.7 v3(116.21,155.7)
CPLD_TCK: length 120.6
  TOP w0.201: R48.1 R45.1 36.06,87.66 46.07,87.66 53.33,94.92 59.43,94.92 63.74,99.24 v2(64.54,99.24) ; R146.2 67.93,91.24 68.26,91.57 70.1,91.57 70.6,92.07 70.6,93.91 v1(69.1,95.4) ; U1.131 v1(113.4,135.6)
  SIG1 w0.15: v2(64.54,99.24) 64.1,98.81 64.1,97.02 66.35,94.77 68.47,94.77 v1(69.1,95.4) 69.37,95.4 75.23,101.27 76.24,101.27 79.01,104.04 79.01,108.1 87.05,116.13 87.2,116.13 96.7,125.63 96.7,133.34 99.43,136.07 107.68,136.07 107.75,136.15 112.85,136.15 v1(113.4,135.6)
CPLD_TDI: length 119.7
  TOP w0.201: U1.136 113.96,133.1 113.07,132.21 109.74,132.21 v1(109.59,132.36) ; R51.1 R47.1 50.66,85.4 53.58,82.48 67.73,82.48 69.18,83.93 69.18,84.54 v2(68.7,85.02) 67.93,85.78 R151.2
  SIG1 w0.15: v1(109.59,132.36) 109.11,131.88 107.18,131.88 105.51,133.55 101.19,133.55 100.95,133.78 98.61,133.78 97.73,132.91 97.73,125.2 90.24,117.71 90.24,114.63 89.77,114.16 87.87,114.16 80.99,107.28 80.99,102.26 78.86,100.13 78.86,99.2 69.75,90.1 69.55,90.1 68.95,89.5 68.95,88.83 68.32,88.19 68.32,85.4 v2(68.7,85.02)
CPLD_TDO: length 131.5
  TOP w0.201: v2(68.95,94.11) 68.57,94.49 65.32,94.49 64.21,93.38 62.49,93.38 60.65,91.54 60.65,88.52 59.75,87.63 U2.15 ; v1(108.6,132.34) R4.2 ; J7.3 48.52,91.11 53.04,95.63 58.61,95.63 63.11,100.13 v1(64.51,100.13)
  SIG1 w0.15: v1(108.6,132.34) 107.01,133.93 103.22,133.93 102.61,134.55 98.83,134.55 97.35,133.07 97.35,125.36 87.47,115.47 87.32,115.47 79.67,107.82 79.67,103.77 70.01,94.11 v2(68.95,94.11) 66.08,94.11 63.44,96.75 63.44,99.08 64.49,100.13 v1(64.51,100.13)
CPLD_TMS: length 116.1
  TOP w0.201: v1(64.51,101.02) 63.28,101.02 58.4,96.14 52.83,96.14 50.85,94.16 R46.1 R49.1 ; v1(113.65,136.45) 114.01,136.1 U1.130 ; R148.2 67.74,95.18 v2(68.27,95.71)
  SIG1 w0.15: v1(113.65,136.45) 112.69,137.42 107.65,137.42 106.97,136.73 99.16,136.73 95.23,132.8 95.23,129.32 93.64,127.72 93.64,123.5 89.54,119.4 83.69,119.4 80.65,116.35 80.65,110.66 78.36,108.37 78.36,104.83 78.03,104.5 77.53,104.5 69.22,96.19 68.75,96.19 v2(68.27,95.71) 68.17,95.61 66.74,95.61 65.19,97.16 65.19,100.33 v1(64.51,101.02)
CPU_9641_INT#: length 122.3
  TOP w0.201: U9.A3 166.51,98.8 v2(174.93,98.8) ; R290.1 v1(104.49,129.72)
  SIG1 w0.15: v1(104.49,129.72) 104.49,129.87 105.82,131.21 109.62,131.21 110.35,131.94 111.94,131.94 112.32,131.56 112.32,124.9 117.01,120.21 123.02,120.21 124.81,118.42 142.06,118.42 150.63,126.99 173.65,126.99 174.45,126.19 174.45,99.28 v2(174.93,98.8)
CPU_I2C_RST#: length 86.5
  TOP w0.201: YJ1.A1_1 v1(89.08,87.45) ; v2(145.38,80.06) C149.1 ; U9.C17 162.53,80.85 158.53,80.85 v1(157.47,81.91)
  SIG1 w0.15: v1(89.08,87.45) 89.44,87.1 137.14,87.1 142.99,81.25 144.19,81.25 v2(145.38,80.06) 155.63,80.06 v1(157.47,81.91)
CPU_I2C_SCL: length 169.8
  TOP w0.201: v1(121.83,119.05) 121.83,121.41 121.43,121.82 R154.1 121.82,122.62 121.82,125.19 121.97,125.34 U1.11 ; v2(104.61,125.2) R307.2 104.61,127.21 104.34,127.47 103.13,127.47 99.68,130.92 99.68,131.5 100.23,132.05 U10.3 ; U9.D13 161.54,85.65 159.06,85.65 v1(155.32,81.91)
  SIG1 w0.15: v1(155.32,81.91) 143.26,81.91 137.41,87.76 93.76,87.76 92.32,89.2 85.12,89.2 82.51,91.8 82.51,106.8 88.22,112.5 90.98,112.5 103.67,125.2 v2(104.61,125.2) 105.19,125.78 110.45,125.78 117.18,119.05 v1(121.83,119.05)
CPU_I2C_SDA: length 165.1
  TOP w0.201: v1(156.46,81.91) 159.14,84.6 162.6,84.6 U9.C14 ; v1(123.43,119.15) 123.43,121.47 123.08,121.82 R158.1 122.67,122.74 122.54,122.86 R157.2 ; R291.1 104.82,131.5 105.02,131.3 105.02,129.47 104.61,129.06 R308.2 105.27,128.2 105.53,127.94 105.53,127.31 106.7,126.14 v2(106.7,125.18)
  SIG1 w0.15: v1(156.46,81.91) 155.26,83.11 142.99,83.11 137.69,88.41 94.03,88.41 92.59,89.86 85.39,89.86 83.17,92.08 83.17,106.53 88.49,111.85 91.25,111.85 102.33,122.92 104.44,122.92 v2(106.7,125.18) 107.24,124.64 109.91,124.64 117.08,117.46 122.09,117.46 123.43,118.81 v1(123.43,119.15)
CPU_KR_RDN0: length 63.9
  TOP w0.127: U9.C9 v1(162.53,91.01)
  SIG1 w0.102: 108.06,98.69 108.04,98.69 107.99,98.64 106.95,98.64 arc(106.94,98.63) 106.94,98.63 arc(106.82,98.6) 106.7,98.56 arc(106.65,98.53) 106.6,98.5 arc(106.58,98.49) 106.57,98.48 arc(106.56,98.48) 106.55,98.47 arc(106.54,98.47) 106.53,98.47 arc(106.52,98.47) 106.51,98.47 YJ1.B7_2
  SIG1 w0.119: v1(162.53,91.01) 162.57,91.06 163.06,91.06 163.39,91.39 163.39,93.22 162.83,93.78 159.82,93.78 158.32,95.28 119.27,95.28 115.86,98.69 108.06,98.69
CPU_KR_RDN1: length 78.8
  TOP w0.127: U9.C12 v1(162.53,87.2)
  SIG1 w0.102: YJ1.B7_1 94.52,98.47 arc(94.53,98.47) 94.54,98.47 arc(94.54,98.47) 94.55,98.47 arc(94.55,98.47) 94.56,98.48 arc(94.57,98.48) 94.59,98.49 arc(94.81,98.6) 95.05,98.64 95.93,98.64 95.98,98.69 96,98.69
  SIG1 w0.119: v1(162.53,87.2) 162.7,87.37 163.06,87.37 163.4,87.71 163.4,88.92 162.98,89.34 159.22,89.34 157.04,91.52 112.44,91.52 112.11,91.19 102.15,91.19 99.28,94.06 99.28,96.5 97.09,98.69 96,98.69
CPU_KR_RDP0: length 63.9
  TOP w0.127: U9.C8 v1(162.53,92.28)
  SIG1 w0.102: 108.06,98.31 108.04,98.31 107.99,98.36 107.05,98.36 arc(107.02,98.36) 106.98,98.35 arc(106.9,98.34) 106.82,98.31 arc(106.79,98.29) 106.75,98.27 arc(106.71,98.24) 106.68,98.2 106.63,98.15 106.5,97.97 106.47,97.92 106.37,97.82 106.14,97.65 arc(106.03,97.29) YJ1.B8_2
  SIG1 w0.119: 108.06,98.31 115.7,98.31 119.11,94.9 158.16,94.9 159.66,93.4 162.68,93.4 163.01,93.06 163.01,91.55 162.9,91.44 162.64,91.44 162.52,91.56 162.52,92.27 v1(162.53,92.28)
CPU_KR_RDP1: length 78.8
  TOP w0.127: U9.C11 v1(162.53,88.47)
  SIG1 w0.102: 96,98.31 95.98,98.31 95.93,98.36 95.05,98.36 arc(94.89,98.33) 94.75,98.26 arc(94.71,98.23) 94.68,98.2 94.64,98.16 94.55,98.04 94.48,97.93 94.38,97.82 94.04,97.6 arc(93.94,97.2) YJ1.B8_1
  SIG1 w0.119: v1(162.53,88.47) 162.53,87.92 162.7,87.75 162.9,87.75 163.02,87.87 163.02,88.77 162.82,88.96 159.06,88.96 156.89,91.14 112.6,91.14 112.27,90.8 101.99,90.8 98.9,93.9 98.9,96.34 96.94,98.31 96,98.31
CPU_KR_TDN0: length 77
  TOP w0.127: U9.B22 v1(165.07,73.23)
  SIG2 w0.104: 107.33,106.36 107.23,106.36 106.8,105.93 106.67,105.8 arc(106.63,105.76) 106.59,105.71 arc(106.4,105.37) 106.33,104.98 YJ1.D8_2
  SIG2 w0.13: 107.33,106.36 107.47,106.5 107.65,106.5 107.8,106.35 107.8,106.16 107.7,106.06 107.7,102.85 118.06,92.48 122.91,92.48 136.63,78.77 150.74,78.77 155.84,73.67 164.94,73.67 165.07,73.54 v1(165.07,73.23)
CPU_KR_TDN1: length 95.7
  TOP w0.127: v1(151.98,89.66) 152.37,89.26 152.37,81.33 159.6,74.1 161.66,74.1 U9.D22
  SIG2 w0.104: 95.38,108.77 95.37,108.75 95.37,108.66 94.88,108.18 94.88,106.65 arc(94.84,106.41) 94.7,106.21 94.48,105.99 94.19,105.7 arc(93.98,105.56) 93.73,105.51 93.68,105.51 arc(93.6,105.52) 93.54,105.57 arc(93.44,105.8) 93.54,106.03 YJ1.D7_1
  SIG2 w0.13: 95.38,108.77 96.7,110.09 98.93,110.09 102.11,113.26 112.31,113.26 136.85,88.72 151.93,88.72 152.23,89.03 152.23,89.4 v1(151.98,89.66)
CPU_KR_TDP0: length 77
  TOP w0.127: U9.B21 v1(165.07,74.5)
  SIG2 w0.104: 107.04,106.64 107.04,106.55 106.42,105.93 arc(106.07,105.78) 105.72,105.93 YJ1.D7_2
  SIG2 w0.13: 107.04,106.64 107.3,106.91 107.82,106.91 108.2,106.52 108.2,105.99 108.1,105.89 108.1,103.01 118.23,92.89 123.08,92.89 136.79,79.17 150.9,79.17 156.01,74.07 164.64,74.07 v1(165.07,74.5)
CPU_KR_TDP1: length 95.7
  TOP w0.127: v1(152.99,89.66) 152.67,89.34 152.67,81.46 159.72,74.41 161.74,74.41 161.9,74.57 U9.D21
  SIG2 w0.104: YJ1.D8_1 94.33,104.98 arc(94.38,105.32) 94.54,105.64 arc(94.56,105.68) 94.59,105.71 arc(94.63,105.76) 94.67,105.8 94.89,106.02 arc(95.09,106.31) 95.15,106.65 95.15,108.06 95.35,108.27 95.56,108.47 95.65,108.47 95.67,108.49
  SIG2 w0.13: 95.67,108.49 96.87,109.68 99.1,109.68 102.28,112.86 112.14,112.86 136.68,88.32 152.1,88.32 152.64,88.86 152.64,89.52 152.78,89.66 v1(152.99,89.66)
CPU_ONLINE_TCK: length 144.9
  TOP w0.201: U2.4 62.77,86.33 62.47,86.03 62.47,85.4 62.84,85.03 U2.2 64.49,85.03 65.01,84.51 R253.2 v2(66.44,83.75) ; v1(166.74,97.85) 166.61,97.85 166.13,97.36 165.07,97.36 U9.B4
  SIG1 w0.15: v2(66.44,83.75) 66.44,89.49 67.7,90.75 69.48,90.75 v1(77.56,98.83)
  SIG2 w0.16: v1(77.56,98.83) 76.66,99.74 76.66,105.46 85.16,113.96 86.64,113.96 90.51,117.82 93.01,117.82 96.67,121.49 100.3,121.49 100.92,122.11 104.65,122.11 104.97,122.42 113.67,122.42 125.2,110.89 133.86,110.89 145.64,99.11 160.14,99.11 161.4,97.85 v1(166.74,97.85)
CPU_ONLINE_TDI: length 127.5
  TOP w0.201: U9.D4 v1(161.26,97.36) ; v2(68.77,87.66) 68.49,87.94 R155.2
  SIG1 w0.15: v2(68.77,87.66) 71.21,87.66 72.45,88.9 72.45,90.68 v1(79.75,97.97)
  SIG2 w0.16: v1(161.26,97.36) 160.27,98.35 145.46,98.35 133.59,110.22 124.93,110.22 113.71,121.44 101.2,121.44 100.57,120.82 96.94,120.82 93.28,117.16 90.78,117.16 86.92,113.29 85.43,113.29 77.33,105.19 77.33,100.56 78.73,99.16 78.73,98.99 v1(79.75,97.97)
CPU_ONLINE_TDO: length 142.2
  TOP w0.127: U9.B10 v1(165.07,89.74)
  TOP w0.201: v2(68.95,92.28) 67.97,92.28 67.64,91.95 62.49,91.95 61.66,91.12 61.66,88.1 59.88,86.33 U2.17 56.46,86.33 56.12,86.67 R254.2
  SIG1 w0.15: v2(68.95,92.28) 70.04,92.28 77.97,100.21 v1(78.36,100.21)
  SIG2 w0.16: v1(78.36,100.21) 78.29,100.28 78.29,100.9 79.65,102.26 79.65,106.19 85.94,112.49 88.66,112.49 92.52,116.35 93.65,116.35 97.28,119.99 100.88,119.99 101.53,120.64 113.37,120.64 124.62,109.4 133.28,109.4 145.23,97.44 154.06,97.44 161.28,90.23 164.59,90.23 v1(165.07,89.74)
CPU_ONLINE_TMS: length 144.5
  TOP w0.201: U9.B13 165.1,85.96 v1(167.37,85.96) ; U2.6 62.93,87.63 62.67,87.89 62.67,88.65 62.95,88.93 U2.8 65.75,88.93 65.9,89.08 R252.2 66.44,89.46 66.66,89.69 68.21,89.69 69.36,88.55 v2(69.59,88.55)
  SIG1 w0.15: v2(69.59,88.55) 70.02,88.97 70.02,89.76 79.75,99.49 v1(79.75,100.26)
  SIG2 w0.16: v1(79.75,100.26) 80.05,100.55 80.05,106.02 86.12,112.09 90.11,112.09 97.59,119.56 101.03,119.56 101.7,120.24 113.21,120.24 124.45,108.99 133.11,108.99 145.07,97.04 153.83,97.04 161.63,89.24 167.21,89.24 167.8,88.65 167.8,86.39 167.37,85.96 v1(167.37,85.96)
CPU_PCIE_RXN0: length 82.3
  TOP w0.127: U9.C3 v1(162.53,98.63)
  SIG1 w0.102: YJ1.B5_1 92.08,97.14 arc(92.17,97.72) 92.42,98.25 arc(92.47,98.32) 92.53,98.39 arc(92.55,98.41) 92.57,98.44 arc(92.61,98.48) 92.65,98.53 92.75,98.63 arc(92.86,98.79) 92.9,98.99 arc(92.91,99.05) 92.95,99.11 93.09,99.25 arc(93.22,99.34) 93.37,99.37 93.37,99.37 93.59,99.37 arc(93.82,99.41) 94.02,99.55 94.02,99.55 94.08,99.61 arc(94.27,99.73) 94.48,99.77 95.97,99.77 96.54,100.34 96.61,100.34 96.63,100.36
  SIG1 w0.119: v1(162.53,98.63) 162.53,98.79 162.23,99.09 160.76,99.09 159.77,98.1 120.51,98.1 111.14,107.47 101.11,107.47 100.33,106.69 100.33,104.07 96.63,100.36
CPU_PCIE_RXN1: length 108
  TOP w0.127: U9.A6 v1(166.34,94.82)
  SIG1 w0.102: YJ1.A5_1 92.08,93.34 arc(92.17,93.92) 92.42,94.45 arc(92.47,94.52) 92.53,94.59 arc(92.55,94.61) 92.57,94.64 arc(92.61,94.68) 92.65,94.73 92.75,94.83 arc(92.88,95.02) 92.93,95.25 92.93,95.43 arc(92.76,95.84) 92.34,96.01 90.67,96.01 90.62,96.07 90.59,96.07
  SIG1 w0.119: 90.59,96.07 89.3,96.07 88.15,97.21 88.15,103.32 88.52,103.68 88.52,105.69 88.42,105.8 88.42,106.71 90.76,109.04 111.75,109.04 121.17,99.62 159.02,99.62 161.08,101.68 163.03,101.68 164.23,100.48 164.23,95.75 164.71,95.27 166.22,95.27 166.34,95.15 v1(166.34,94.82)
CPU_PCIE_RXN2: length 63.4
  TOP w0.127: U9.C6 v1(162.53,94.82)
  SIG1 w0.102: 108.45,100.21 108.42,100.21 108.37,100.26 107.74,100.26 107.25,99.77 106.48,99.77 arc(106.27,99.73) 106.08,99.61 106.02,99.55 arc(105.82,99.41) 105.59,99.37 105.37,99.37 105.37,99.37 arc(105.22,99.34) 105.09,99.25 104.95,99.11 arc(104.91,99.05) 104.9,98.99 arc(104.86,98.79) 104.75,98.63 104.65,98.53 arc(104.61,98.48) 104.57,98.44 arc(104.55,98.41) 104.53,98.39 arc(104.47,98.32) 104.42,98.25 arc(104.17,97.72) 104.08,97.14 YJ1.B5_2
  SIG1 w0.119: v1(162.53,94.82) 162.08,95.28 160.21,95.28 158.93,96.56 119.86,96.56 116.21,100.21 108.45,100.21
CPU_PCIE_RXN3: length 68.3
  TOP w0.127: U9.A9 v1(166.34,91.01)
  SIG1 w0.102: YJ1.A5_2 104.08,93.34 arc(104.17,93.92) 104.42,94.45 arc(104.47,94.52) 104.53,94.59 arc(104.55,94.61) 104.57,94.64 arc(104.61,94.68) 104.65,94.73 104.75,94.83 arc(104.86,94.99) 104.9,95.19 arc(104.91,95.25) 104.95,95.31 105.09,95.45 arc(105.22,95.54) 105.37,95.57 105.37,95.57 105.59,95.57 arc(105.82,95.61) 106.02,95.75 106.08,95.81 arc(106.27,95.93) 106.48,95.97 107.74,95.97 107.79,95.92 107.81,95.92
  SIG1 w0.119: v1(166.34,91.01) 166.34,91.08 165.97,91.45 164.89,91.45 164.6,91.17 164.6,90.58 164.16,90.15 160.15,90.15 157.23,93.06 118.54,93.06 115.67,95.92 107.81,95.92
CPU_PCIE_RXP0: length 82.3
  TOP w0.127: U9.C2 v1(162.53,99.9)
  SIG1 w0.102: YJ1.B4_1 91.44,98.36 arc(91.82,98.22) 92.18,98.4 92.29,98.54 arc(92.3,98.55) 92.31,98.56 arc(92.34,98.6) 92.36,98.63 arc(92.41,98.68) 92.45,98.72 92.55,98.82 92.55,98.82 arc(92.6,98.9) 92.62,98.99 arc(92.66,99.16) 92.76,99.31 92.9,99.45 arc(93.11,99.6) 93.37,99.65 93.59,99.65 arc(93.72,99.67) 93.82,99.74 93.89,99.81 arc(94.16,99.99) 94.48,100.05 95.85,100.05 96.34,100.54 96.34,100.61 96.36,100.63
  SIG1 w0.119: v1(162.53,99.9) 162.1,99.47 160.6,99.47 159.61,98.48 120.67,98.48 111.3,107.85 100.95,107.85 99.95,106.85 99.95,104.23 96.36,100.63
CPU_PCIE_RXP1: length 108
  TOP w0.127: U9.A5 v1(166.34,96.09)
  SIG1 w0.102: YJ1.A4_1 91.84,94.67 arc(92.17,94.74) 92.45,94.92 92.55,95.02 92.55,95.02 arc(92.62,95.13) 92.65,95.25 92.65,95.43 arc(92.56,95.65) 92.34,95.74 90.67,95.74 90.62,95.68 90.59,95.68
  SIG1 w0.119: 90.59,95.68 89.14,95.68 87.77,97.05 87.77,103.47 88.14,103.84 88.14,105.54 88.04,105.64 88.04,106.86 90.6,109.43 111.91,109.43 121.33,100 158.87,100 160.92,102.06 163.19,102.06 164.61,100.64 164.61,95.91 164.87,95.65 165.9,95.65 v1(166.34,96.09)
CPU_PCIE_RXP2: length 63.4
  TOP w0.127: U9.C5 v1(162.53,96.09)
  SIG1 w0.102: YJ1.B4_2 103.44,98.36 arc(103.82,98.22) 104.18,98.4 104.29,98.54 arc(104.3,98.55) 104.31,98.56 arc(104.34,98.6) 104.36,98.63 arc(104.41,98.68) 104.45,98.72 104.55,98.82 104.55,98.82 arc(104.6,98.9) 104.62,98.99 arc(104.66,99.16) 104.76,99.31 104.9,99.45 arc(105.11,99.6) 105.37,99.65 105.59,99.65 arc(105.72,99.67) 105.82,99.74 105.89,99.81 arc(106.16,99.99) 106.48,100.05 107.14,100.05 107.62,100.54 108.37,100.54 108.42,100.59 108.45,100.59
  SIG1 w0.119: v1(162.53,96.09) 162.1,95.66 160.37,95.66 159.09,96.94 120.02,96.94 116.37,100.59 108.45,100.59
CPU_PCIE_RXP3: length 68.3
  TOP w0.127: U9.A8 v1(166.34,92.28)
  SIG1 w0.102: 107.81,96.3 107.79,96.3 107.74,96.25 106.48,96.25 arc(106.16,96.19) 105.89,96.01 105.82,95.94 arc(105.72,95.87) 105.59,95.85 105.37,95.85 arc(105.11,95.8) 104.9,95.65 104.76,95.51 arc(104.66,95.36) 104.62,95.19 arc(104.6,95.1) 104.55,95.02 104.45,94.92 arc(104.41,94.88) 104.36,94.83 arc(104.34,94.79) 104.31,94.76 arc(104.3,94.75) 104.29,94.74 104.18,94.6 arc(103.82,94.42) 103.44,94.56 YJ1.A4_2
  SIG1 w0.119: v1(166.34,92.28) 165.89,91.83 164.73,91.83 164.22,91.32 164.22,90.74 164.01,90.53 160.3,90.53 157.39,93.44 118.69,93.44 115.83,96.3 107.81,96.3
CPU_PCIE_TXN0: length 94.4
  TOP w0.127: U9.B16 v1(163.8,82.12)
  SIG2 w0.104: YJ1.D4_1 91.92,106.07 arc(91.96,106.07) 92,106.07 arc(92.03,106.08) 92.06,106.08 arc(92.06,106.08) 92.06,106.08 arc(92.08,106.08) 92.09,106.09 92.09,106.09 arc(92.14,106.1) 92.18,106.11 arc(92.25,106.13) 92.31,106.16 arc(92.43,106.23) 92.54,106.33 arc(92.59,106.44) 92.62,106.56 92.62,106.57 arc(92.62,106.6) 92.62,106.62 92.62,107.51 arc(92.72,108.08) 93,108.57 93.06,108.63 arc(93.12,108.71) 93.14,108.81 93.16,108.83
  SIG2 w0.13: v1(163.8,82.12) 163.83,82.15 164.35,82.15 164.69,82.49 164.69,84.43 163.08,86.05 161.26,86.05 155.44,91.87 135.91,91.87 112.96,114.82 101.47,114.82 98.29,111.64 95.97,111.64 93.16,108.83
CPU_PCIE_TXN1: length 88.6
  TOP w0.127: U9.D16 v1(161.26,82.12)
  SIG2 w0.104: YJ1.C5_1 92.08,101.22 arc(92.16,101.63) 92.4,101.98 92.51,102.1 92.65,102.24 arc(92.81,102.46) 92.89,102.71 arc(92.89,102.77) 92.89,102.82 92.89,102.92 arc(92.91,103.03) 92.98,103.12 93.03,103.18 arc(93.2,103.29) 93.4,103.33 94.88,103.33 95.94,104.39 95.94,106.55 96.56,107.17 96.66,107.17
  SIG2 w0.13: 96.66,107.17 97.19,107.7 99.32,107.7 102.92,111.31 111.5,111.31 138.42,84.38 157.61,84.38 159.46,82.53 161.1,82.53 161.26,82.37 v1(161.26,82.12)
CPU_PCIE_TXN2: length 79.9
  TOP w0.127: U9.B19 v1(165.07,78.31)
  SIG2 w0.104: 104.96,107.34 104.96,107.32 104.89,107.25 104.89,106.62 arc(104.89,106.59) 104.89,106.55 arc(104.82,106.27) 104.65,106.04 104.4,105.78 arc(104.16,105.43) 104.08,105.02 YJ1.D5_2
  SIG2 w0.13: v1(165.07,78.31) 165.07,78.66 164.9,78.82 164.71,78.82 164.61,78.73 164.61,77.66 163.02,76.06 155.82,76.06 150.8,81.08 137.29,81.08 110.31,108.06 105.33,108.06 104.96,107.69 104.96,107.34
CPU_PCIE_TXN3: length 85.7
  TOP w0.127: U9.D19 v1(161.26,78.31)
  SIG2 w0.104: 101.68,107.87 101.66,107.85 101.56,107.85 100.45,106.73 100.45,104.83 101.68,103.6 104.42,103.6 arc(104.75,103.46) 104.89,103.13 104.89,102.82 arc(104.89,102.77) 104.89,102.71 arc(104.81,102.46) 104.65,102.24 104.51,102.1 104.4,101.98 arc(104.16,101.63) 104.08,101.22 YJ1.C5_2
  SIG2 w0.13: v1(161.26,78.31) 161.26,78.62 161.13,78.75 159.69,78.75 158.16,80.28 154.46,80.28 152.01,82.73 137.85,82.73 110.97,109.61 104.52,109.61 103.42,109.61 101.68,107.87
CPU_PCIE_TXP0: length 94.4
  TOP w0.127: U9.B15 v1(163.8,83.39)
  SIG2 w0.104: 93.45,108.54 arc(93.32,108.48) 93.2,108.39 arc(92.97,107.98) 92.89,107.51 92.89,106.62 arc(92.89,106.59) 92.89,106.55 arc(92.85,106.36) 92.76,106.18 arc(92.71,106.11) 92.65,106.04 92.46,105.85 92.32,105.68 92.25,105.54 92.16,105.45 91.82,105.24 arc(91.7,104.84) YJ1.D5_1
  SIG2 w0.13: v1(163.8,83.39) 163.8,82.68 163.92,82.56 164.18,82.56 164.28,82.66 164.28,84.27 162.91,85.64 161.09,85.64 155.27,91.47 135.74,91.47 112.8,114.41 101.63,114.41 98.46,111.23 96.14,111.23 93.45,108.54
CPU_PCIE_TXP1: length 88.6
  TOP w0.127: U9.D15 v1(161.26,83.39)
  SIG2 w0.104: YJ1.C4_1 91.43,102.17 arc(91.81,102.01) 92.2,102.17 92.4,102.36 92.46,102.43 arc(92.57,102.58) 92.62,102.75 arc(92.62,102.78) 92.62,102.82 92.62,102.92 arc(92.67,103.13) 92.78,103.31 92.79,103.31 92.84,103.37 arc(93.1,103.54) 93.4,103.6 94.77,103.6 95.67,104.5 95.67,106.66 96.36,107.35 96.36,107.44 96.37,107.45
  SIG2 w0.13: 96.37,107.45 97.02,108.11 99.15,108.11 102.75,111.71 111.66,111.71 138.59,84.79 157.77,84.79 159.63,82.94 160.8,82.94 v1(161.26,83.39)
CPU_PCIE_TXP2: length 79.9
  TOP w0.127: U9.B18 v1(165.07,79.58)
  SIG2 w0.104: 104.56,107.34 104.56,107.32 104.62,107.25 104.62,106.62 arc(104.62,106.6) 104.62,106.57 arc(104.57,106.39) 104.46,106.23 104.2,105.97 arc(103.81,105.81) 103.42,105.97 YJ1.D4_2
  SIG2 w0.13: 104.56,107.34 104.56,107.86 105.16,108.47 110.48,108.47 137.46,81.49 150.97,81.49 155.98,76.47 162.85,76.47 164.21,77.83 164.21,78.89 164.54,79.23 164.72,79.23 v1(165.07,79.58)
CPU_PCIE_TXP3: length 85.7
  TOP w0.127: U9.D18 v1(161.26,79.58)
  SIG2 w0.104: 101.39,108.15 101.39,108.06 100.18,106.85 100.18,104.72 101.56,103.33 104.42,103.33 arc(104.56,103.27) 104.62,103.13 104.62,102.82 arc(104.62,102.78) 104.62,102.75 arc(104.57,102.58) 104.46,102.43 104.4,102.36 104.2,102.17 arc(103.81,102.01) 103.42,102.17 YJ1.C4_2
  SIG2 w0.13: v1(161.26,79.58) 160.83,79.15 159.86,79.15 158.32,80.68 154.63,80.68 152.18,83.14 138.02,83.14 111.14,110.02 104.52,110.02 103.26,110.02 101.39,108.15
CPU_RESERVE1: length 119.8
  TOP w0.127: U9.B37 v1(165.07,54.18)
  TOP w0.201: v2(140.71,137.09) R250.2
  SIG1 w0.15: v1(171.95,124.01) 171.95,123.55 171.8,123.4 171.8,60.71 166.92,55.84 166.92,55.4 166.48,54.96 165.85,54.96 v1(165.07,54.18)
  SIG2 w0.16: v2(140.71,137.09) 140.71,140.76 143.53,143.59 153.87,143.59 170.95,126.51 170.95,125 v1(171.95,124.01)
CPU_RESERVE2: length 117.8
  TOP w0.127: U9.B38 v1(165.07,52.91)
  TOP w0.201: v2(145.51,143.03) 145.51,143.03 145.51,140.62 143.12,138.23 R251.2
  SIG1 w0.15: v1(165.07,52.91) 165.72,53.56 166.99,53.56 167.94,54.52 167.94,55.78 172.83,60.67 172.83,120.24 v1(173.04,120.45)
  SIG2 w0.16: v1(173.04,120.45) 170.55,122.93 170.55,126.34 153.85,143.04 145.52,143.04 v2(145.51,143.03)
CR: length 406.6
  TOP w0.201: v1(64.58,107.88) 64.01,107.31 63.06,107.31 62.46,107.91 21.44,107.91 9.92,119.43 8.75,119.43 8.5,119.69 R180.1 R185.2 ; R176.2 365.18,119.1 v2(365.05,118.97)
  SIG1 w0.15: v1(64.58,107.88) 65.47,106.99 67.52,106.99 80.32,119.78 89.38,119.78 93.26,123.66 93.26,127.88 94.85,129.47 94.85,132.96 99,137.11 106.77,137.11 107.45,137.79 113.58,137.79 114.44,136.94 114.44,124.83 118.3,120.96 123.34,120.96 125.12,119.18 141.75,119.18 150.45,127.89 330.37,127.89 341.62,116.64 358.38,116.64 361.18,119.43 364.23,119.43 364.69,118.97 v2(365.05,118.97)
FAN0_E2_WP: length 205.6
  TOP w0.201: R54.2 129.28,122.86 v2(129.02,122.61)
  SIG1 w0.15: v2(129.02,122.61) 129.28,122.86 129.28,125.78 130.42,126.93 143.46,126.93 165.85,149.32 293.35,149.32 306.44,162.41 306.44,169.73 J2.6
FAN0_EN: length 209.7
  TOP w0.201: R327.2 v2(132.07,122.74) 132.07,122.25 R333.1
  SIG1 w0.15: J2.2 316.6,169.73 316.6,166.84 315.45,165.69 311.86,165.69 293.98,147.8 167.56,147.8 144.15,124.39 132.83,124.39 132.07,123.62 v2(132.07,122.74)
FAN0_LED1: length 203.4
  TOP w0.201: U1.27 v2(129.97,125.78)
  SIG1 w0.15: J2.5 308.98,169.73 308.98,164.41 293.51,148.94 166.01,148.94 143.62,126.55 130.74,126.55 v2(129.97,125.78)
FAN0_LED2: length 204
  TOP w0.201: v1(129.91,124.78) 129.47,125.22 U1.26
  SIG1 w0.15: v1(129.91,124.78) 129.91,124.9 131.18,126.17 143.77,126.17 166.16,148.56 293.66,148.56 310.2,165.1 J2.12
  BOTTOM w0.201: v3(128.91,124.71) 129.85,124.71 v1(129.91,124.78)
FAN0_POWER_OK#: length 218.8
  TOP w0.201: v2(305.93,163.78) 306.03,163.88 327.14,163.88 328.54,165.28 R97.1 ; v1(132.87,128.35) 133.47,127.75 U1.34 133.47,126.16 133.48,126.16 133.48,124.95 133.21,124.69 R161.1
  SIG1 w0.15: v1(132.87,128.35) 132.43,128.8 132.43,129.43 132.7,129.7 136.28,129.7 137.66,128.32 143.78,128.32 165.54,150.07 292.23,150.07 v2(305.93,163.78)
FAN0_PRESENT_IN#: length 218.6
  TOP w0.201: v1(133.78,129.24) 133.78,128.11 133.97,127.92 U1.35 133.97,126.42 134.23,126.16 R160.1 ; R96.1 329.55,165.03 327.9,163.38 306.66,163.38 v2(305.72,162.44)
  SIG1 w0.15: v1(133.78,129.24) 133.78,129.24 135.72,127.31 143.3,127.31 165.69,149.7 292.98,149.7 v2(305.72,162.44)
FAN0_PWM: length 212.7
  TOP w0.201: U1.28 130.47,125.53 130.39,125.45 130.39,123.95 v2(130.16,123.72)
  SIG1 w0.15: v2(130.16,123.72) 130.71,123.72 131.51,122.92 131.51,122.41 131.94,121.97 132.32,121.97 132.7,122.35 132.7,123.5 133.21,124.01 144.3,124.01 167.72,147.43 294.13,147.43 312.02,165.31 315.61,165.31 317.82,167.52 J2.15
FAN0_SCL: length 238.5
  TOP w0.201: U8.5 96.72,151.61 96.64,151.69 v2(96.64,153.16) R228.2
  SIG2 w0.16: J2.4 314.06,169.63 314.06,167.82 310.76,164.52 303.84,164.52 302.77,165.59 218.22,165.59 214.76,162.13 182.59,162.13 179.84,164.88 157.49,164.88 155.72,166.65 145.88,166.65 144.51,165.28 139.31,165.28 129.66,155.63 123.62,155.63 121.12,158.13 112.55,158.13 111.73,157.3 98.33,157.3 97.29,156.26 97.29,155.39 96.64,154.74 v2(96.64,153.16)
